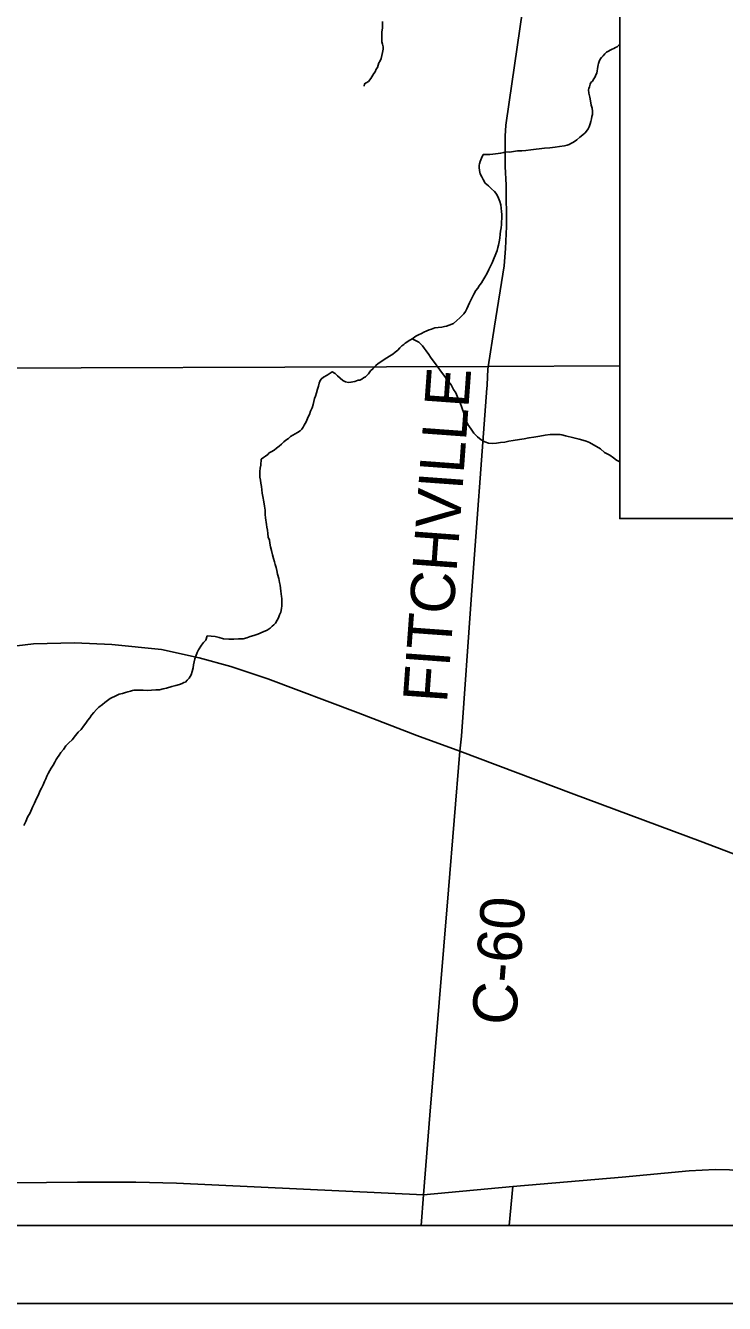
# Model space of a CAD drawing. Extents: x 0 to 34, y 0 to 22.
# Drawn here: x 2.927 to 3.825, y 14 to 15.642 of the extents above; entities that cross this region are included whole.
import ezdxf

# ---------------------------------------------------------------- set-up
doc = ezdxf.new("R2010")
doc.units = 0
for name, color, linetype in [('GM_X_Corporation', 7, 'Continuous'), ('GM_X_County_Road', 7, 'Continuous'), ('GM_X_County_Road_Text', 7, 'Continuous'), ('GM_X_Minor_River', 7, 'Continuous'), ('GM_X_State_Route', 7, 'Continuous'), ('GM_X_Township_Road', 7, 'Continuous'), ('SH_Data', 7, 'Continuous'), ('SH_Text', 7, 'Continuous')]:
    doc.layers.add(name, color=color, linetype=linetype)

msp = doc.modelspace()

# ---------------------------------------------------------------- linework, layer by layer
at = {"layer": 'GM_X_Corporation'}
for points in [[(2.1, 20.2456), (2.1, 14.1), (8.0383, 14.1), (8.035, 14.2498), (8.0349, 14.2572), (8.0297, 14.4963), (8.0262, 14.6555), (8.0153, 15.2273), (7.992, 16.4534)], [(2.7477, 15.8824), (2.7366, 15.2014), (3.5209, 15.2041), (3.6901, 15.2048), (3.6901, 15.7256)]]:
    msp.add_lwpolyline(points, dxfattribs=at)
msp.add_lwpolyline([(3.6901, 15.2048), (3.5209, 15.2041), (2.7366, 15.2014), (2.7422, 14.8151), (2.7753, 14.1537), (2.7761, 14.1), (8.0383, 14.1), (8.035, 14.2498), (8.0349, 14.2572), (8.0297, 14.4963), (8.0262, 14.6555), (8.0153, 15.2273), (6.9496, 15.2134), (6.7394, 15.212), (6.1026, 15.2145), (5.9099, 15.2138), (5.9099, 15.0085), (3.6901, 15.0085)], close=True, dxfattribs=at)
at = {"layer": 'GM_X_County_Road'}
for points in [[(3.5195, 15.1803), (3.5207, 15.2006), (3.5211, 15.2036), (3.5293, 15.2558), (3.5414, 15.3335), (3.5433, 15.3555), (3.5444, 15.384), (3.544, 15.4372), (3.5428, 15.4611), (3.5426, 15.4998), (3.5435, 15.5143), (3.548, 15.5436), (3.572, 15.7092), (3.6074, 15.9775), (3.6369, 16.2036), (3.6567, 16.349), (3.7031, 16.7163), (3.7483, 17.0786), (3.7604, 17.1798), (3.7595, 17.1946), (3.7574, 17.3264), (3.7557, 17.5159), (3.7523, 17.7146)], [(3.4349, 14.1), (3.438, 14.1396), (3.4462, 14.242), (3.4702, 14.5314), (3.4844, 14.7097), (3.4868, 14.7289), (3.499, 14.9044), (3.5192, 15.1763), (3.5195, 15.1793), (3.5195, 15.1803)], [(3.438, 14.1396), (3.5526, 14.1503), (3.6932, 14.1622), (3.779, 14.1705), (3.8127, 14.1721), (3.8312, 14.1717), (3.8682, 14.168), (3.9631, 14.1577), (4.0699, 14.1466), (4.1681, 14.1364), (4.2765, 14.1249), (4.3352, 14.1209)], [(2.7512, 14.1526), (2.7755, 14.1532), (2.7942, 14.1536), (2.9934, 14.1556), (3.0302, 14.1558), (3.0685, 14.1556), (3.1205, 14.1545), (3.438, 14.1396)]]:
    msp.add_lwpolyline(points, dxfattribs=at)
at = {"layer": 'GM_X_Minor_River'}
for points in [[(3.3852, 15.6473), (3.3851, 15.6389), (3.3843, 15.634), (3.3842, 15.6317), (3.3842, 15.6298), (3.3845, 15.6245), (3.3845, 15.6211), (3.3852, 15.6184), (3.3859, 15.6146), (3.3859, 15.6119), (3.3851, 15.6074), (3.3835, 15.5998), (3.3819, 15.596), (3.3807, 15.5941), (3.3788, 15.5884), (3.3772, 15.5862), (3.3757, 15.5828), (3.3741, 15.5805), (3.3726, 15.5783), (3.3702, 15.5741), (3.3671, 15.57), (3.3641, 15.5685), (3.3622, 15.567), (3.3618, 15.5666), (3.3622, 15.567), (3.3617, 15.5643)], [(3.6901, 15.6175), (3.6889, 15.6167), (3.6866, 15.6148), (3.6847, 15.6137), (3.6824, 15.6126), (3.6801, 15.6119), (3.6732, 15.6078), (3.6709, 15.6059), (3.6686, 15.6032), (3.6667, 15.601), (3.6648, 15.5987), (3.6636, 15.5957), (3.6628, 15.5934), (3.6624, 15.5915), (3.662, 15.5893), (3.6616, 15.5866), (3.6608, 15.584), (3.6604, 15.5809), (3.6592, 15.5786), (3.6584, 15.5764), (3.6569, 15.5737), (3.6549, 15.5707), (3.653, 15.5688), (3.6522, 15.5666), (3.651, 15.5632), (3.6502, 15.5613), (3.6498, 15.5594), (3.6505, 15.5552), (3.6516, 15.5502), (3.6523, 15.5453), (3.6534, 15.5399), (3.6545, 15.5358), (3.6548, 15.5319), (3.6548, 15.5278), (3.654, 15.5251), (3.6536, 15.5221), (3.6528, 15.5187), (3.652, 15.5156), (3.6508, 15.5119), (3.6496, 15.5092), (3.6473, 15.5066), (3.6454, 15.5043), (3.6427, 15.5017), (3.6388, 15.4987), (3.635, 15.4953), (3.6308, 15.4923), (3.6273, 15.4905), (3.625, 15.4894), (3.6224, 15.4882), (3.6189, 15.4875), (3.6128, 15.4865), (3.6071, 15.4858), (3.6003, 15.4851), (3.5934, 15.4844), (3.5759, 15.4823), (3.5695, 15.4816), (3.5641, 15.481), (3.5588, 15.481), (3.5535, 15.4803), (3.5485, 15.4796), (3.5436, 15.4797), (3.5409, 15.4789), (3.5371, 15.4782), (3.5337, 15.4775), (3.5302, 15.4772), (3.5268, 15.4768), (3.523, 15.4765), (3.5181, 15.4766), (3.5146, 15.4762), (3.5123, 15.4717), (3.5107, 15.4675), (3.5099, 15.4645), (3.5095, 15.4626), (3.5095, 15.4596), (3.5098, 15.4557), (3.5109, 15.4516), (3.5128, 15.4477), (3.5146, 15.4443), (3.5172, 15.4397), (3.5214, 15.4362), (3.5251, 15.4324), (3.5293, 15.4289), (3.5323, 15.4251), (3.5341, 15.4205), (3.536, 15.4159), (3.5371, 15.4117), (3.5378, 15.4075), (3.5381, 15.4033)], [(3.5381, 15.4033), (3.5384, 15.3992), (3.5384, 15.3942), (3.5379, 15.3897), (3.5379, 15.3866), (3.5375, 15.3821), (3.5367, 15.3779), (3.5362, 15.3741), (3.5358, 15.3688), (3.535, 15.3642), (3.5342, 15.3601), (3.5334, 15.357), (3.5326, 15.3532), (3.5263, 15.3373), (3.5239, 15.3328), (3.522, 15.3286), (3.5197, 15.3241), (3.5169, 15.3188), (3.5142, 15.3147), (3.5123, 15.3117), (3.5107, 15.3094), (3.5092, 15.3075), (3.5076, 15.3045), (3.5053, 15.3015), (3.5026, 15.297), (3.5007, 15.2936), (3.4987, 15.2894), (3.4971, 15.2856), (3.4952, 15.2818), (3.4936, 15.2781), (3.4917, 15.2747), (3.4898, 15.2716), (3.4871, 15.269), (3.4844, 15.2664), (3.4809, 15.263), (3.4763, 15.2593), (3.471, 15.257), (3.4675, 15.2556), (3.4649, 15.2552), (3.4614, 15.2545), (3.4569, 15.2542), (3.4523, 15.2535), (3.4481, 15.252), (3.445, 15.2509), (3.442, 15.2498), (3.4385, 15.2483), (3.4355, 15.2464), (3.4313, 15.2446), (3.429, 15.2435), (3.4267, 15.242), (3.424, 15.2401), (3.4205, 15.2379), (3.4182, 15.2364), (3.4163, 15.2353), (3.4144, 15.2338), (3.4125, 15.2323), (3.4102, 15.2304), (3.4075, 15.2278), (3.4048, 15.2248), (3.4014, 15.2225), (3.3983, 15.2199), (3.3944, 15.2173), (3.391, 15.215), (3.3795, 15.2079), (3.3768, 15.2053), (3.3734, 15.2016), (3.3699, 15.1982), (3.3672, 15.1944), (3.3633, 15.1907), (3.361, 15.1892), (3.3587, 15.1877), (3.3561, 15.1866), (3.3538, 15.1862), (3.3519, 15.1855), (3.3496, 15.1847), (3.3473, 15.1844), (3.3446, 15.1837), (3.3416, 15.1833), (3.3378, 15.1841), (3.3344, 15.1861), (3.331, 15.1888), (3.3276, 15.1918), (3.3242, 15.1949), (3.3205, 15.1972), (3.3182, 15.1954), (3.3143, 15.1928), (3.3094, 15.1902), (3.3067, 15.1883), (3.3051, 15.186), (3.3039, 15.1826), (3.3028, 15.1788), (3.3016, 15.175), (3.3004, 15.1701), (3.2992, 15.166), (3.298, 15.1629), (3.2972, 15.1591), (3.296, 15.1553), (3.2948, 15.1508), (3.2929, 15.1466), (3.2913, 15.1425), (3.2893, 15.1383)], [(3.4232, 15.2396), (3.4319, 15.2351), (3.4338, 15.2335), (3.4368, 15.2305), (3.4387, 15.2274), (3.4413, 15.2239), (3.4447, 15.2193), (3.4469, 15.2159), (3.454, 15.2063), (3.4566, 15.2025), (3.4596, 15.1986), (3.4626, 15.1944), (3.466, 15.1898), (3.4697, 15.1852), (3.4735, 15.1802), (3.4764, 15.1745), (3.4794, 15.1703), (3.4813, 15.1657), (3.4835, 15.1607), (3.4853, 15.1561), (3.4868, 15.1527), (3.4879, 15.1489), (3.4894, 15.1454), (3.4901, 15.1428), (3.4912, 15.139), (3.4927, 15.1344), (3.4949, 15.1294), (3.499, 15.1233), (3.5027, 15.1183), (3.5072, 15.1137), (3.5121, 15.1098), (3.5167, 15.1071), (3.5212, 15.1055), (3.5265, 15.1051), (3.5315, 15.1054), (3.5368, 15.1061), (3.5425, 15.1068), (3.5475, 15.1079), (3.5532, 15.109), (3.5612, 15.11), (3.5673, 15.1111), (3.5734, 15.1121), (3.5798, 15.1132), (3.5875, 15.1146), (3.5943, 15.1157), (3.6008, 15.1164), (3.6061, 15.1167), (3.6103, 15.1166), (3.6133, 15.1166), (3.6156, 15.1162), (3.6202, 15.115), (3.6236, 15.1142), (3.6277, 15.113), (3.6327, 15.1118), (3.638, 15.1106), (3.6425, 15.1094), (3.6467, 15.1082), (3.6512, 15.1063), (3.6652, 15.0981), (3.6705, 15.0935), (3.6773, 15.09), (3.6818, 15.0865), (3.6859, 15.0838), (3.6901, 15.0813)], [(3.2893, 15.1383), (3.2874, 15.1338), (3.2858, 15.1308), (3.2847, 15.1285), (3.2831, 15.1259), (3.2816, 15.1236), (3.2793, 15.1213), (3.2762, 15.1191), (3.267, 15.1139), (3.2643, 15.1116), (3.2612, 15.1094), (3.2586, 15.1071), (3.2555, 15.1041), (3.2524, 15.1015), (3.249, 15.0989), (3.2459, 15.0966), (3.2424, 15.0944), (3.2398, 15.0929), (3.2378, 15.0907), (3.2348, 15.0888), (3.2325, 15.0869), (3.2294, 15.0847), (3.2289, 15.0771), (3.2281, 15.0733), (3.2277, 15.0691), (3.2276, 15.0657), (3.2276, 15.0619), (3.2283, 15.0577), (3.229, 15.0539), (3.2297, 15.0497), (3.2304, 15.0455), (3.2308, 15.0413), (3.2315, 15.0368), (3.2329, 15.0299), (3.2336, 15.0246), (3.2343, 15.0192), (3.2346, 15.0139), (3.2349, 15.0094), (3.2364, 15.001), (3.2367, 14.9976), (3.2374, 14.9937), (3.2381, 14.9892), (3.2385, 14.9846), (3.2399, 14.9808), (3.2403, 14.977), (3.2413, 14.9724), (3.2428, 14.9675), (3.2439, 14.9621), (3.2453, 14.9572), (3.2464, 14.953), (3.2475, 14.9495), (3.2486, 14.9457), (3.2493, 14.9419), (3.2504, 14.9373), (3.2519, 14.9316), (3.2526, 14.9289), (3.253, 14.9263), (3.2537, 14.9229), (3.254, 14.919), (3.2547, 14.9152), (3.2551, 14.9118), (3.2554, 14.9084), (3.2558, 14.9057), (3.2561, 14.9023), (3.2561, 14.8993), (3.256, 14.8966), (3.2556, 14.8928), (3.2544, 14.8883), (3.2528, 14.8849), (3.2517, 14.8811), (3.2497, 14.878), (3.2478, 14.8743), (3.2455, 14.872), (3.2435, 14.8701), (3.2409, 14.8679), (3.237, 14.8653), (3.2321, 14.8631), (3.2252, 14.8601), (3.2198, 14.8583), (3.2152, 14.8568), (3.2111, 14.8553), (3.2061, 14.8542), (3.2004, 14.8539), (3.1943, 14.8536), (3.1878, 14.8537), (3.181, 14.8542), (3.1753, 14.8557), (3.1704, 14.8569), (3.1601, 14.8578), (3.1582, 14.8521), (3.1551, 14.8495), (3.1528, 14.8457), (3.1489, 14.8397), (3.147, 14.8363), (3.1442, 14.8284), (3.1434, 14.8246), (3.1426, 14.8204), (3.1418, 14.8166), (3.1406, 14.8121), (3.1394, 14.8079), (3.1382, 14.8056)], [(3.1382, 14.8056), (3.1367, 14.8034), (3.1344, 14.8007), (3.1321, 14.7985), (3.1301, 14.7977), (3.1279, 14.7966), (3.1244, 14.7952), (3.1198, 14.7941), (3.1145, 14.7926), (3.1076, 14.7908), (3.1034, 14.7897), (3.0989, 14.7886), (3.0939, 14.7883), (3.0886, 14.788), (3.0829, 14.7877), (3.0776, 14.7881), (3.0723, 14.7882), (3.0684, 14.7882), (3.0658, 14.7879), (3.0639, 14.7875), (3.0616, 14.7868), (3.0582, 14.7857), (3.0551, 14.785), (3.0513, 14.7839), (3.0471, 14.7828), (3.0433, 14.7813), (3.0352, 14.7772), (3.0318, 14.7746), (3.0283, 14.7724), (3.0257, 14.7697), (3.021, 14.766), (3.0176, 14.763), (3.0145, 14.7592), (3.0114, 14.7558), (3.0091, 14.7524), (3.0068, 14.7494), (3.0041, 14.7456), (3.001, 14.7419), (2.9979, 14.7377), (2.9944, 14.734), (2.991, 14.7298), (2.9867, 14.7242), (2.9821, 14.7204), (2.9786, 14.7163), (2.9752, 14.7118), (2.9721, 14.708), (2.9697, 14.7046), (2.9678, 14.7016), (2.9659, 14.699), (2.9643, 14.6956), (2.962, 14.6918), (2.9597, 14.688), (2.9577, 14.685), (2.9558, 14.6808), (2.9542, 14.6774), (2.9527, 14.674), (2.9511, 14.6706), (2.9491, 14.6665), (2.9472, 14.6623), (2.9452, 14.6582), (2.9433, 14.6536), (2.9409, 14.6487), (2.9382, 14.643), (2.9355, 14.6378), (2.9327, 14.6306), (2.9293, 14.6249), (2.9269, 14.6192), (2.9246, 14.6143)]]:
    msp.add_lwpolyline(points, dxfattribs=at)
at = {"layer": 'GM_X_State_Route'}
msp.add_lwpolyline([(2.1, 14.6851), (2.3144, 14.728), (2.4286, 14.752), (2.7425, 14.8145), (2.8311, 14.8324), (2.8864, 14.8416), (2.937, 14.8474), (2.9895, 14.8488), (3.0376, 14.8469), (3.1012, 14.8401), (3.1496, 14.8296), (3.1902, 14.8183), (3.2378, 14.8024), (3.354, 14.7588), (3.4295, 14.7299), (3.4844, 14.7097), (3.6309, 14.6542), (3.7935, 14.5941), (4.0411, 14.4997)], dxfattribs=at)
at = {"layer": 'GM_X_Township_Road'}
msp.add_line((3.5478, 14.1), (3.5526, 14.1503), dxfattribs=at)
at = {"layer": 'SH_Data'}
for p, q in [((2.1, 14.1), (8.9, 14.1)), ((2, 14), (9, 14))]:
    msp.add_line(p, q, dxfattribs=at)
at = {"layer": 'SH_Text'}
msp.add_lwpolyline([(3.6901, 15.7256), (5.9099, 15.7256), (5.9099, 15.0085), (3.6901, 15.0085)], close=True, dxfattribs=at)

# ---------------------------------------------------------------- texts
at = {"layer": 'GM_X_County_Road_Text'}
for s, rotation, p in [('FITCHVILLE', 85.8383, (3.468, 14.7708)), ('C-60', 85.5486, (3.5563, 14.3561))]:
    msp.add_text(s, height=0.05682, rotation=rotation, dxfattribs=at).set_placement(p)

doc.saveas('drawing.dxf')
